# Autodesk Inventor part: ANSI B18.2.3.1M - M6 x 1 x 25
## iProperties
Comments: To add or edit properties for Autodesk Inventor files, use iProperties.
Created: 2005-06
Part Number: ANSI B18.2.3.1M - M6 x 1 x 25
Vendor: Autodesk Inc.
Document SubType Name: Modeling
Designer: John Blackburn
Material: Default
Description: Metric Hex Cap Screw
Standard: ANSI B18.2.3.1M
Size Designation: M6 x 1 x 25
Alert: To add or edit properties for Autodesk Inventor files, use iProperties.
Control State: 0
Master: False
Checked Out: False
Shininess: 64.0
Length Units: 11269
Angle Units: 11279
Time Units: 11290
Mass Units: 11283
Length Display Precision: 3
Angle Display Precision: 2
Compacted: True
EGR: 1
Classification: un/spsc 31161513
Density: 0.0
Volumn: 0.0
Area: 0.0
PropertySet Name: Model Information
Author: John Blackburn
Revision Number: 8
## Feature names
1. Body [Revolution]
2. Head [Extrusion]
3. Chamfer1 [Revolution]
4. Chamfer2
